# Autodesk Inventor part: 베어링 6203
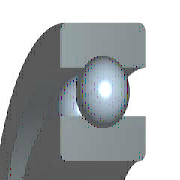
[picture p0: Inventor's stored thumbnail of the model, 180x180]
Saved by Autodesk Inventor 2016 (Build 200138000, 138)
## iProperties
IsCustomPart: 0
Company: 한국ATC센터
Created: 2015-11
Part Number: 베어링 6203
Material: 강철, 연강
Description: 깊은 그루브 볼 베어링
Document SubType Name: Modeling
Standard: KS B 2023
Designer: mdu
Standards Organization: KS
Language: ko-KR
Size Designation: 6203 - 17 x 40 x 12
Categories: <MemberInstance><Categories><Category DisplayName="샤프트 부품" InternalName="7f7aeb1f-a693-4053-b835-cee3144e0d98" Mnemonic="SHFT"><Category DisplayName="베어링" Inter
Density: 1 g/cm^3
Appearance: 크롬 - 광택
Author: mdu
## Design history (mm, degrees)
sketch "스케치" dims "d0" = 5.98 (= -0.26 x WD + 0.26 x BD)
  geometry: L1 (3.01, 14.25)-(8.99, 14.25); L2 (6, 14.25)-(6, 11.26); L3 (6, 14.25)-(6, 17.24); L4 (3.778, 12.249)-(0, 12.249); L5 (0, 8.5)-(12, 8.5); L6 (3.778, 16.251)-(0, 16.251); L7 (0, 20)-(12, 20); L8 (12, 8.5)-(12, 12.249); L9 (8.222, 12.249)-(12, 12.249); L10 (8.222, 16.251)-(12, 16.251); L11 (12, 20)-(12, 16.251); L12 (-1.4, 0)-(8.4, 0) reference; L13 (0, -0.3)-(0, 5.3) reference
  constraints: 22 end point, 4 point on line, 2 collinear, 2 perpendicular, 2 symmetric about line, 1 midpoint, 1 parallel, 14 other
  dimensions: "d9" = 17 diameter of L5 L12 (= WD); "d11" = 40 diameter of L7 L12 (= BD); "d12" = 12 distance between parallel lines of L8 L13 (= KB); "d13" = 24.498 diameter of L9 L12 (= 0.326 x BD + 0.674 x WD)
revolve "본체" stored, may be unused: angle "d6" = 90 deg
revolve "볼" stored, may be unused: angle "d7" = 90 deg
pattern_circular "IDS_ARRAYBALL[SIMPL:T]" dims angle "d3" = 360 deg
body "Solid1"
fillet "모깎기1" dims "d1" = 0.6 (= KRS)
other parameters: "WD" = 17 [user parameter; used in 5 equation terms], "BD" = 40 [user parameter; used in 5 equation terms], "KB" = 12 [user parameter; used in 1 equation term], "KRS" = 0.6 [user parameter; used in 1 equation term], "d4" = 0, "d5" = 0, "d8" = 0, "d14" = 0, "d15" = 0, "BBA" = 0 [user parameter], "BC0" = 4750000 [user parameter], "BC" = 9560000 [user parameter], "WR" = 8.5 (= 0.5 x WD) [user parameter]
